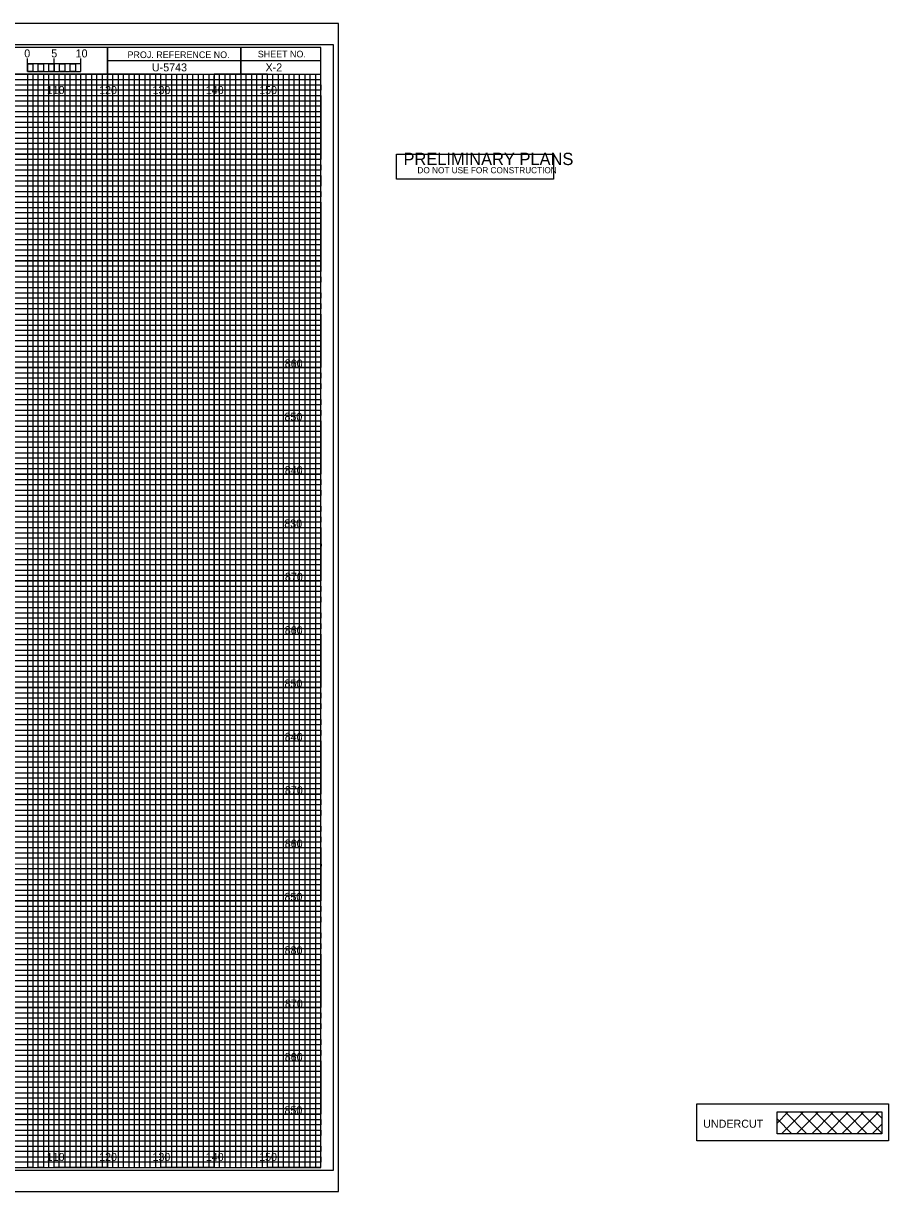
# Model space of a CAD drawing. Extents: x -13 to 426, y -4 to 214.
# Drawn here: x 264.2 to 426.5, y -4.5 to 214.5 of the extents above; entities that cross this region are included whole.
import ezdxf

# ---------------------------------------------------------------- set-up
doc = ezdxf.new("R2010")
doc.units = 0
for name, color, linetype in [('Prop Grid Mask', 7, 'Continuous'), ('Prop Road Sect_ Recs - UC (Outline)', 7, 'Continuous'), ('Prop VPI Label', 7, 'Continuous'), ('Prop XS Bar Scale Labels', 7, 'Continuous'), ('Prop XS Elevation Labels', 7, 'Continuous'), ('Prop XS Offset Labels', 7, 'Continuous'), ('Prop XS Project Number', 7, 'Continuous'), ('Prop XS Sheet Number', 7, 'Continuous'), ('Sheet Cross Section CELL', 7, 'Continuous'), ('Sheet Cross Section Grid Major CELL', 7, 'Continuous'), ('Sheet Cross Section Grid Middle CELL', 7, 'Continuous'), ('Sheet Cross Section Grid Minor 1 CELL', 7, 'Continuous'), ('Sheet Cross Section Grid Minor 2 CELL', 7, 'Continuous'), ('Sheet Cross Section Scale CELL', 7, 'Continuous'), ('Sheet Cutting Line CELL', 7, 'Continuous'), ('Sheet DOT Grid CELL', 7, 'Continuous'), ('Sheet Plot Border Inside CELL', 7, 'Continuous'), ('Sheet Plot Border Outside CELL', 7, 'Continuous'), ('Sheet Sticker Preliminary CELL', 7, 'Continuous')]:
    doc.layers.add(name, color=color, linetype=linetype)

msp = doc.modelspace()

# ---------------------------------------------------------------- linework, layer by layer
at = {"layer": 'Prop Grid Mask'}
msp.add_lwpolyline([(390.49, 11.99), (426.45, 11.99), (426.45, 5), (390.49, 5)], close=True, dxfattribs=at)
at = {"layer": 'Prop Road Sect_ Recs - UC (Outline)'}
for p, q in [((405.53, 8.33), (407.64, 10.44)), ((405.53, 9.12), (408.3, 6.35)), ((406.37, 6.35), (410.46, 10.44)), ((407.04, 10.44), (411.13, 6.35)), ((409.2, 6.35), (413.29, 10.44)), ((409.87, 10.44), (413.96, 6.35)), ((412.03, 6.35), (416.12, 10.44)), ((412.69, 10.44), (416.79, 6.35)), ((414.86, 6.35), (418.95, 10.44)), ((415.52, 10.44), (419.61, 6.35)), ((417.69, 6.35), (421.78, 10.44)), ((418.35, 10.44), (422.44, 6.35)), ((420.51, 6.35), (424.61, 10.44)), ((421.18, 10.44), (425.16, 6.46)), ((424.01, 10.44), (425.16, 9.29)), ((423.34, 6.35), (425.16, 8.16))]:
    msp.add_line(p, q, dxfattribs=at)
msp.add_lwpolyline([(405.53, 10.44), (425.16, 10.44), (425.16, 6.35), (405.53, 6.35)], close=True, dxfattribs=at)
at = {"layer": 'Sheet Cross Section CELL'}
for p, q in [((305, 210), (305, 205)), ((305, 205), (305, 210)), ((280, 207.5), (280, 205)), ((320, 207.49), (280, 207.49)), ((280, 205), (320, 205))]:
    msp.add_line(p, q, dxfattribs=at)
for points in [[(320, 210), (0, 210), (0, 0), (320, 0)], [(280, 210), (260, 210), (260, 205.03), (280, 205.03)], [(320, 210), (280, 210), (280, 205), (320, 205)]]:
    msp.add_lwpolyline(points, close=True, dxfattribs=at)
at = {"layer": 'Sheet Cross Section Grid Major CELL'}
for p, q in [((270, 0), (270, 205)), ((290, 205), (280, 205)), ((280, 205), (280, 0)), ((290, 0), (290, 205)), ((310, 205), (300, 205)), ((300, 205), (300, 0)), ((310, 0), (310, 205)), ((280, 0), (270, 0)), ((300, 0), (290, 0)), ((320, 0), (310, 0)), ((320, 0), (320, 0))]:
    msp.add_line(p, q, dxfattribs=at)
for points in [[(0, 200), (320, 200), (320, 190), (0, 190)], [(0, 180), (320, 180), (320, 170), (0, 170)], [(0, 160), (320, 160), (320, 150), (0, 150)], [(0, 140), (320, 140), (320, 130), (0, 130)], [(0, 120), (320, 120), (320, 110), (0, 110)], [(0, 100), (320, 100), (320, 90), (0, 90)], [(0, 80), (320, 80), (320, 70), (0, 70)], [(0, 60), (320, 60), (320, 50), (0, 50)], [(0, 40), (320, 40), (320, 30), (0, 30)], [(0, 20), (320, 20), (320, 10), (0, 10)]]:
    msp.add_lwpolyline(points, dxfattribs=at)
at = {"layer": 'Sheet Cross Section Grid Middle CELL'}
for points in [[(0, 205), (275, 205)], [(260, 205), (264.99, 205), (264.99, 0), (275, 0), (275, 205), (285, 205), (285, 0), (295, 0), (295, 205), (305, 205), (305, 0), (315, 0), (315, 205)], [(0, 185), (320, 185), (320, 195), (0, 195)], [(0, 165), (320, 165), (320, 175), (0, 175)], [(0, 145), (320, 145), (320, 155), (0, 155)], [(0, 125), (320, 125), (320, 135), (0, 135)], [(0, 105), (320, 105), (320, 115), (0, 115)], [(0, 85), (320, 85), (320, 95), (0, 95)], [(0, 65), (320, 65), (320, 75), (0, 75)], [(0, 45), (320, 45), (320, 55), (0, 55)], [(0, 25), (320, 25), (320, 35), (0, 35)], [(0, 5), (320, 5), (320, 15), (0, 15)]]:
    msp.add_lwpolyline(points, dxfattribs=at)
at = {"layer": 'Sheet Cross Section Grid Minor 1 CELL'}
msp.add_line((0, 204), (320, 204), dxfattribs=at)
for points in [[(0, 203), (270, 203), (320, 203), (320, 202), (0, 202)], [(0, 201), (320, 201), (320, 199), (0, 199)], [(0, 198), (320, 198), (320, 197), (0, 196.98)], [(0, 196), (320, 196), (320, 194), (0, 194)], [(0, 193), (320, 193), (320, 192), (0, 192)], [(0, 191), (320, 191), (320, 189), (0, 189)], [(0, 188), (320, 188), (320, 187), (0, 187)], [(0, 186), (320, 186), (320, 184), (0, 184)], [(0, 183), (320, 183), (320, 182), (0, 182)], [(0, 181), (320, 181), (320, 179), (0, 179)], [(0, 178), (320, 178), (320, 177), (0, 177)], [(0, 176), (320, 176), (320, 173.95), (320, 173), (320, 172), (0, 172)], [(0, 174), (320, 174), (320, 173), (0, 173)], [(0, 171), (320, 171), (320, 169), (0, 169.03)], [(0, 169.03), (320, 169), (320, 168), (0, 168)], [(0, 167), (320, 167), (320, 166), (0, 166)], [(0, 164), (320, 164), (320, 163), (0, 163)], [(0, 162), (320, 162), (320, 161), (0, 161)], [(-0.07, 158.89), (320, 158.89), (320, 157.88), (-0.07, 157.88)], [(0, 157), (320, 157), (320, 156), (0, 156)], [(0, 154), (320, 154), (320, 153), (0, 153)], [(0, 152), (320, 152), (320, 151), (0, 151)], [(0, 149), (320, 149), (320, 148), (0, 148)], [(0, 147), (320, 147), (320, 146), (0, 146)], [(0, 144), (320, 144), (320, 143), (0, 143)], [(0, 142), (320, 142), (320, 141), (0, 141)], [(0, 139), (320, 139), (319.99, 137.98), (0, 138)], [(0, 137), (320, 137), (320, 136), (0, 136)], [(0, 134), (320, 134), (320, 133), (0, 133)], [(0, 132), (320, 132), (320, 131), (0, 131)], [(0, 129), (320, 129), (320, 128), (0, 128)], [(0, 127), (320, 127), (320, 126), (0, 126)], [(0, 124), (320, 124), (320, 123), (0, 123)], [(0, 122), (320, 122), (320, 121), (0, 121)], [(0, 119), (320, 119), (320, 118), (0, 118)], [(0, 116.99), (320.07, 116.91), (320, 116), (0, 116)], [(0, 114), (320, 114), (320, 113), (0, 113)], [(0, 112), (320, 112), (320, 111), (0, 111)], [(0, 109), (320, 109), (320, 108), (0, 108)], [(0, 107), (320, 107), (320, 106), (0, 106)], [(0, 104), (320, 104), (320, 103), (0, 103)], [(0, 102), (320, 102), (320, 101), (0, 101)], [(0, 99), (320, 99), (320, 98), (0, 98)], [(0, 97), (320, 97), (320, 96), (0, 96)], [(0, 94), (320, 94), (320, 93), (0, 93)], [(0, 92), (320, 92), (320, 91), (0, 91)], [(0, 89), (320, 89), (320, 88), (0, 88)], [(0, 87), (320, 87), (320, 86), (0, 86)], [(0, 84), (320, 84), (320, 83), (0, 83)], [(0, 82), (320, 82), (320, 81), (0, 81)], [(0, 79), (320, 79), (319.99, 77.98), (0, 78)], [(0, 77), (320, 77), (320, 76), (0, 76)], [(0, 74), (320, 74), (320, 73), (0, 73)], [(0, 72), (320, 72), (320, 71), (0, 71)], [(0, 69), (320, 69), (320, 68), (0, 68)], [(0, 67), (320, 67), (320, 66), (0, 66)], [(0, 64), (320, 64), (320, 63), (0, 63)], [(0, 62), (320, 62), (320, 61), (0, 61)], [(0, 59), (320, 59), (320, 58), (0, 58)], [(0, 56.99), (320.07, 56.91), (320, 56), (0, 56)], [(0, 54), (320, 54), (320, 53), (0, 53)], [(0, 52), (320, 52), (320, 51), (0, 51)], [(0, 49), (320, 49), (320, 48), (0, 48)], [(0, 47), (320, 47), (320, 46), (0, 46)], [(0, 44), (320, 44), (320, 43), (0, 43)], [(0, 42), (320, 42), (320, 41), (0, 41)], [(0, 39), (320, 39), (320, 38), (0, 38)], [(0, 37), (320, 37), (320, 36), (0, 36)], [(0, 34), (320, 34), (320, 33), (0, 33)], [(0, 32), (320, 32), (320, 31), (0, 31)], [(0, 29), (320, 29), (320, 28), (0, 28)], [(0, 27), (320, 27), (320, 26), (0, 26)], [(0, 24), (320, 24), (320, 23), (0, 23)], [(0, 22), (320, 22), (320, 21), (0, 21)], [(0, 19), (320, 19), (320, 18), (0, 18)], [(0, 17), (320, 17), (320, 16), (0, 16)], [(0, 14), (320, 14), (320, 13), (0, 13)], [(0, 12), (320, 12), (320, 11), (0, 11)], [(0, 9), (320, 9), (320, 8), (0, 8)], [(0, 7), (320, 7), (320, 6), (0, 6)], [(0, 4), (320, 4), (320, 3), (0, 3)], [(0, 2), (320, 2), (320, 1), (0, 1)]]:
    msp.add_lwpolyline(points, dxfattribs=at)
at = {"layer": 'Sheet Cross Section Grid Minor 2 CELL'}
for p, q in [((267, 205), (266.01, 205)), ((266.01, 205), (266.01, 0)), ((267, 0), (267, 205)), ((269, 205), (268, 205)), ((268, 205), (268, 0)), ((269, 0), (269, 205)), ((266.01, 0), (265, 0)), ((268, 0), (267, 0))]:
    msp.add_line(p, q, dxfattribs=at)
for points in [[(270, 0), (270.98, 0), (270.98, 205), (272, 205), (272, 0)], [(272, 0), (273, 0), (273, 205), (274.05, 205), (274.05, 0)], [(275, 0), (276, 0), (276, 205), (277, 205), (277, 0)], [(277, 0), (278, 0), (278, 205), (279, 205), (279, 0)], [(280, 0), (281, 0), (281, 205), (282, 205), (282, 0)], [(282, 0), (283, 0), (283, 205), (284, 205), (284, 0)], [(285, 0), (286, 0), (286, 205), (287, 205), (287, 0)], [(287, 0), (288, 0), (288, 205), (289, 205), (289, 0)], [(290, 0), (291, 0), (291, 205), (292, 205), (292, 0)], [(292, 0), (293, 0), (293, 205), (294, 205), (294, 0)], [(295, 0), (296, 0), (296, 205), (297, 205), (297, 0)], [(297, 0), (298, 0), (298, 205), (299, 205), (299, 0)], [(300, 0), (301, 0), (301, 205), (302, 205), (302, 0)], [(302, 0), (303, 0), (303, 205), (304, 205), (304, 0)], [(305, 0), (306, 0), (306, 205), (307, 205), (307, 0)], [(307, 0), (308, 0), (308, 205), (309, 205), (309, 0)], [(310, 0), (311, 0), (311, 205), (312, 205), (312, 0)], [(312, 0), (313, 0), (313, 205), (314, 205), (314, 0)], [(315, 0), (316, 0), (316, 205), (317, 205), (317, 0)], [(317, 0), (318, 0), (318, 205), (319, 205), (319, 0)]]:
    msp.add_lwpolyline(points, dxfattribs=at)
at = {"layer": 'Sheet Cross Section Scale CELL'}
for p, q in [((265, 205.49), (265, 207.9)), ((265, 206.9), (265, 207.9)), ((270, 205.49), (270, 207.9)), ((275, 205.49), (275, 207.9)), ((275, 206.9), (275, 207.9))]:
    msp.add_line(p, q, dxfattribs=at)
for points in [[(275, 206.9), (265, 206.9), (265, 205.49), (275, 205.49)], [(265, 206.9), (266, 206.9), (266, 205.49), (265, 205.49)], [(267, 206.9), (268, 206.9), (268, 205.49), (267, 205.49)], [(269, 206.9), (270, 206.9), (270, 205.49), (269, 205.49)], [(271, 206.9), (272, 206.9), (272, 205.49), (271, 205.49)], [(273, 206.9), (274, 206.9), (274, 205.49), (273, 205.49)]]:
    msp.add_lwpolyline(points, close=True, dxfattribs=at)
at = {"layer": 'Sheet Cutting Line CELL'}
for p, q in [((323.3, 214.5), (-13.4, 214.5)), ((-13.4, -4.5), (323.3, -4.5))]:
    msp.add_line(p, q, dxfattribs=at)
at = {"layer": 'Sheet DOT Grid CELL'}
for p, q in [((270, 0), (270, 204.69)), ((280, 0), (280, 204.69)), ((290, 0), (290, 204.69)), ((300, 0), (300, 204.69)), ((310, 0), (310, 204.69)), ((0, 200), (320, 200)), ((0, 190), (320, 190)), ((0, 180), (320, 180)), ((0, 170), (320, 170)), ((0, 160), (320, 160)), ((0, 150), (320, 150)), ((0, 140), (320, 140)), ((0, 130), (320, 130)), ((0, 120), (320, 120)), ((0, 110), (320, 110)), ((0, 100), (320, 100)), ((0, 90), (320, 90)), ((0, 80), (320, 80)), ((0, 70), (320, 70)), ((0, 60), (320, 60)), ((0, 50), (320, 50)), ((0, 40), (320, 40)), ((0, 30), (320, 30)), ((0, 20), (320, 20)), ((0, 10), (320, 10))]:
    msp.add_line(p, q, dxfattribs=at)
at = {"layer": 'Sheet Plot Border Inside CELL'}
msp.add_lwpolyline([(-10.8, -0.5), (322.4, -0.5), (322.4, 210.5), (-10.8, 210.5)], close=True, dxfattribs=at)
at = {"layer": 'Sheet Plot Border Outside CELL'}
msp.add_lwpolyline([(-13.4, -4.5), (323.3, -4.5), (323.3, 214.5), (-13.4, 214.5)], close=True, dxfattribs=at)
at = {"layer": 'Sheet Sticker Preliminary CELL'}
msp.add_lwpolyline([(334.2, 185.31), (334.2, 190.01), (363.6, 190.01), (363.6, 185.31)], close=True, dxfattribs=at)

# ---------------------------------------------------------------- texts
at = {"layer": 'Prop VPI Label'}
msp.add_text('UNDERCUT', height=1.5, dxfattribs=at).set_placement((391.69, 7.48))
at = {"layer": 'Prop XS Bar Scale Labels'}
for s, p in [('5', (269.47, 208.12)), ('10', (274.04, 208.12))]:
    msp.add_text(s, height=1.5, dxfattribs=at).set_placement(p)
at = {"layer": 'Prop XS Elevation Labels'}
for s, p in [('860', (313.24, 150)), ('850', (313.19, 140)), ('840', (313.24, 130)), ('830', (313.16, 120)), ('870', (313.28, 110)), ('860', (313.24, 100)), ('850', (313.19, 90)), ('840', (313.24, 80)), ('870', (313.28, 70)), ('860', (313.24, 60)), ('850', (313.19, 50)), ('880', (313.22, 40)), ('870', (313.28, 30)), ('860', (313.24, 20)), ('850', (313.19, 10))]:
    msp.add_text(s, height=1.5, dxfattribs=at).set_placement(p)
at = {"layer": 'Prop XS Offset Labels'}
for s, p in [('110', (268.62, 201.25)), ('120', (278.44, 201.25)), ('130', (288.44, 201.25)), ('140', (298.44, 201.25)), ('150', (308.44, 201.25)), ('110', (268.62, 1.25)), ('120', (278.44, 1.25)), ('130', (288.44, 1.25)), ('140', (298.44, 1.25)), ('150', (308.44, 1.25))]:
    msp.add_text(s, height=1.5, dxfattribs=at).set_placement(p)
at = {"layer": 'Prop XS Project Number'}
msp.add_text('U-5743', height=1.5, dxfattribs=at).set_placement((288.34, 205.5))
at = {"layer": 'Prop XS Sheet Number'}
msp.add_text('X-2', height=1.5, dxfattribs=at).set_placement((309.64, 205.5))
at = {"layer": 'Sheet Cross Section CELL'}
for s, p in [('PROJ. REFERENCE NO.', (283.77, 207.99)), ('SHEET NO.', (308.19, 208.12))]:
    msp.add_text(s, height=1.25, dxfattribs=at).set_placement(p)
at = {"layer": 'Sheet Cross Section Scale CELL'}
msp.add_text('0', height=1.5, dxfattribs=at).set_placement((264.41, 208.12))
at = {"layer": 'Sheet Sticker Preliminary CELL'}
for s, height, p in [('PRELIMINARY PLANS', 2.304, (335.5, 187.94)), ('DO NOT USE FOR CONSTRUCTION', 1.152, (338.12, 186.4))]:
    msp.add_text(s, height=height, dxfattribs=at).set_placement(p)

doc.saveas('drawing.dxf')
